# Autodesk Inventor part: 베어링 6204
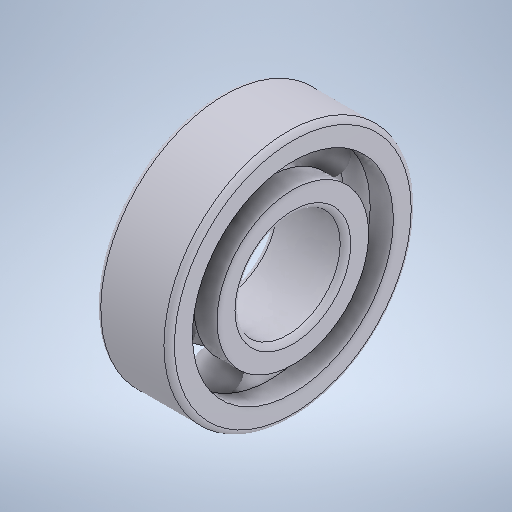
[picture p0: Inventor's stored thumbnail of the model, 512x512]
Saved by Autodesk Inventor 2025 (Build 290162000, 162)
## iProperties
Created: 2024-08
Part Number: 베어링 6204
Material: 강철, 연강
Description: 깊은 그루브 볼 베어링
Document SubType Name: Modeling
Designer: 학생
Density: 7.86 g/cm^3
Appearance: 기본값
Author: jhkim
Sending System: Autodesk Inventor 2025
Preprocessor: ST-DEVELOPER v20
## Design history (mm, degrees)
feature "Solid1"
feature "Solid1:1"
feature "Solid1:2"
feature "Solid1:3"
feature "Solid1:4"
feature "Solid1:5"
feature "Solid1:6"
feature "Solid1:7"
feature "Solid1:8"
node "솔리드1"
node "솔리드2"
node "솔리드3"
node "솔리드4"
node "솔리드5"
node "솔리드6"
node "솔리드7"
node "솔리드8"
node "솔리드9"
